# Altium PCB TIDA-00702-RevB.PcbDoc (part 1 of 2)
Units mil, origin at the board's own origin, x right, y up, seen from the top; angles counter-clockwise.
Board outline 3789.41 x 3228.35 mil, 2 copper layers (Top Layer, Bottom Layer), stack 62 mil thick; 129 components, 54 nets, 298 pads, 91 vias.
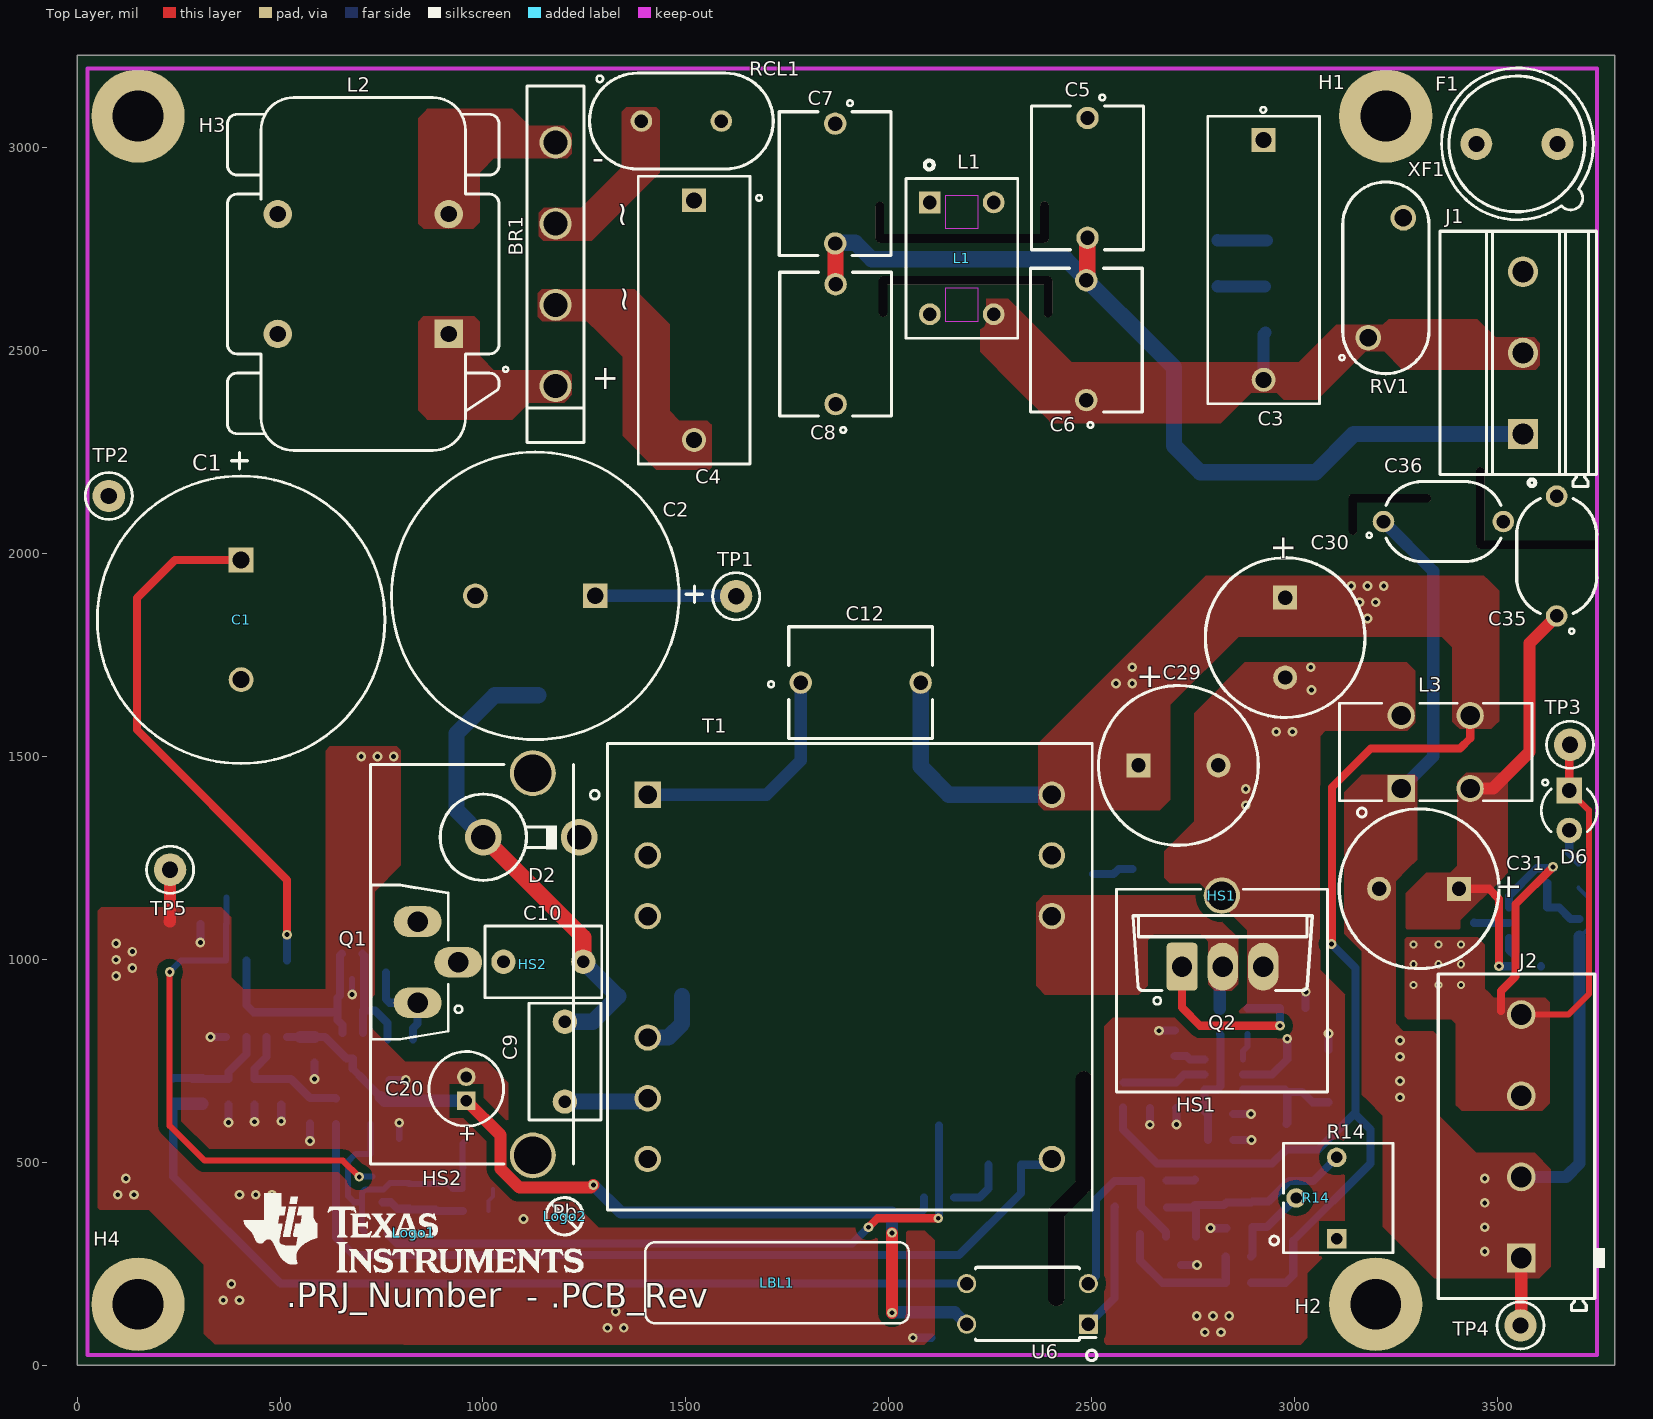
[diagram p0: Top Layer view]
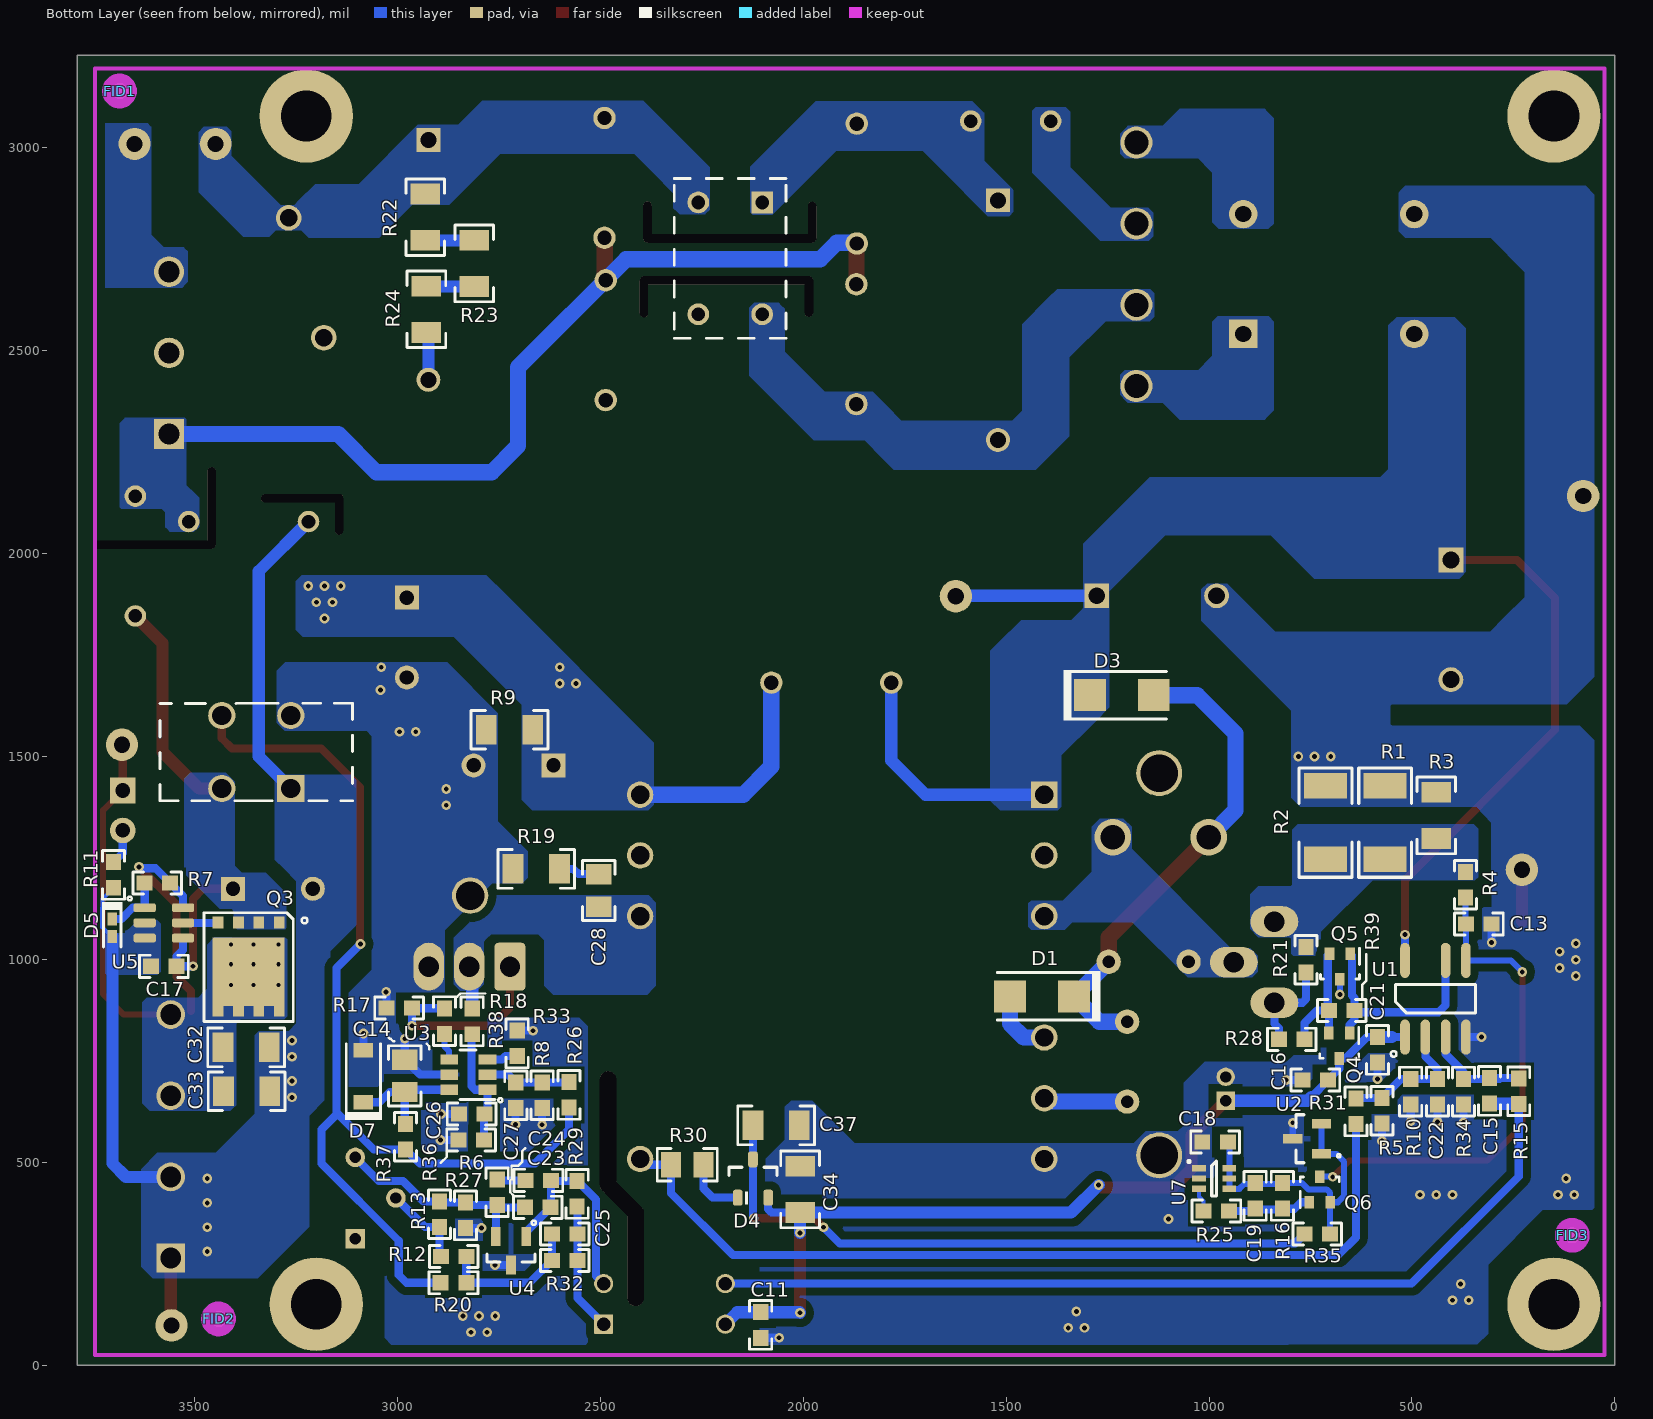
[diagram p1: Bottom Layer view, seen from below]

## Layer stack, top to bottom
Top Solder: solder mask 0.4, Solder Resist, Dk 3.5
Top Layer: signal copper 1.4
Dielectric1: core 59.2, FR-4, Dk 4.8
Bottom Layer: signal copper 1.4
Bottom Solder: solder mask 0.4, Solder Resist, Dk 3.5

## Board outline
0,0 0,3228.35 3789.41,3228.35 3789.41,0

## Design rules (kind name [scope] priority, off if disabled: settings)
AcuteAngle [All] p1: minimum=4.50000000000000E+0001 checktracksonly=FALSE
AssemblyTestPointUsage [All] p1: valid=2
Clearance Clearance_1 [IsSMTPin vs IsVia] p1: gap=8
Clearance Clearance_Poly [InPolygon] p2: gap=20
Clearance [All] p3: gap=8
ComponentClearance ComponentClearance_Shunt [InComponentClass('Header') vs InComponentClass('Shunt')] p1: gap=0 collisioncheckmode=3 verticalgap=0 showdistances=FALSE
ComponentClearance ComponentClearance_MountingHoles_FiducialMarks [InComponentClass('Mounting Holes') vs InComponentClass('FiducialMark')] p2: gap=20 collisioncheckmode=3 verticalgap=10 showdistances=FALSE
ComponentClearance ComponentClearance_Logo [InComponentClass('Logo')] p3: gap=0 collisioncheckmode=3 verticalgap=0 showdistances=FALSE
ComponentClearance ComponentClearance_ScrewToNut [(HasFootprint('NY PMS 440 0025 PH')) vs (HasFootprint('Keystone_1902C'))] p4: gap=5 collisioncheckmode=3 verticalgap=10 showdistances=FALSE
ComponentClearance ComponentClearance_MountingHoles [InComponentClass('Mounting Holes')] p5: gap=50 collisioncheckmode=3 verticalgap=100000 showdistances=FALSE
ComponentClearance ComponentClearance_SmallPassives [HasFootprint('0201*') or HasFootprint('0402*') or HasFootprint('0508') or HasFootprint('0603*') or HasFootprint('0612') or HasFootprint('0805*') or HasFootprint('0815*') or HasFootprint('0830*') or HasFootprint('1206*') or HasFootprint('1210*') or HasFootprint('1808*') or HasFootprint('1812*') or HasFootprint('1825*') or HasFootprint('2010*') or HasFootprint('2220*') or HasFootprint('2225*') or HasFootprint('2512*') or HasFootprint('2728*') or HasFootprint('3518*') vs HasFootprint('0201*') or HasFootprint('0402*') or HasFootprint('0508') or HasFootprint('0603*') or HasFootprint('0612') or HasFootprint('0805*') or HasFootprint('0815*') or HasFootprint('0830*') or HasFootprint('1206*') or HasFootprint('1210*') or HasFootprint('1808*') or HasFootprint('1812*') or HasFootprint('1825*') or HasFootprint('2010*') or HasFootprint('2220*') or HasFootprint('2225*') or HasFootprint('2512*') or HasFootprint('2728*') or HasFootprint('3518*')] p6: gap=10 collisioncheckmode=3 verticalgap=10 showdistances=FALSE
DiffPairsRouting [All] p1: maxlimit=100 minlimit=10 mostfreqgap=10 toplayer_minwidth=15 toplayer_maxwidth=15 toplayer_prefwidth=15 bottomlayer_minwidth=15 bottomlayer_maxwidth=15 bottomlayer_prefwidth=15 maxuncoupledlength=1000
FabricationTestPointUsage TestPointUsage [All] p1: valid=2 allowmultiple=FALSE
FabricationTestpoint Testpoint [All] p1: side=3 testpointundercomponent=TRUE minsize=40 maxsize=100 preferedsize=60 minholesize=0 maxholesize=40 preferedholesize=32 testpointgrid=1 allowsidetop=TRUE allowsidebottom=TRUE usegrid=TRUE gridtolerance=0.01
FanoutControl Fanout_LCC [IsLCC] p1: bgadir=Out bgaviamode=Centered fanoutstyle=Auto fanoutdirection=Alternating viagrid=1 // Fanout_LCC (Default Rule)
FanoutControl Fanout_BGA [IsBGA] p2: bgadir=Out bgaviamode=Centered fanoutstyle=Auto fanoutdirection=Alternating viagrid=1 // Fanout_BGA (Default Rule)
FanoutControl Fanout_Default [All] p4: bgadir=Out bgaviamode=Centered fanoutstyle=Auto fanoutdirection=Alternating viagrid=1 // Fanout_Default (Default Rule)
FanoutControl Fanout_Small [(CompPinCount < 5)] p5: bgadir=Out bgaviamode=Centered fanoutstyle=Auto fanoutdirection=OutThenIn viagrid=1 // Fanout_Small (Default Rule)
Height [All] p1: minheight=0 maxheight=2000 prefheight=100
HoleSize [All] p1: absolutevalues=TRUE maxlimit=251 minlimit=8 maxpercent=80.000 minpercent=20.000
MinimumAnnularRing MinimumAnnularRing_ThermalPadVias [IsVia and InAnyComponent] p1: minimumring=5.91
MinimumAnnularRing [All] p2: minimumring=9
MinimumSolderMaskSliver MinimumSolderMaskSliver_Logo [InComponentClass('Logo') vs InComponentClass('Logo')] p1: minsoldermaskwidth=0.7
MinimumSolderMaskSliver [All] p2: minsoldermaskwidth=3.94
PlaneConnect [All] p1: planeconnectstyle=Direct reliefexpansion=10 reliefentries=4 reliefconductorwidth=10 reliefairgap=10
PolygonConnect [All] p1: connectstyle=Direct reliefconductorwidth=10 reliefentries=4 polygonreliefangle="90 Angle" airgapwidth=10
RoutingVias ThermalPadVias [IsVia and InAnyComponent] p1: holewidth=7.87 width=19.68 viastyle="Through Hole" minholewidth=7.87 minwidth=19.68 maxholewidth=12.99 maxwidth=23.62
RoutingVias [All] p2: holewidth=12 width=24 viastyle="Through Hole" minholewidth=7.87 minwidth=24 maxholewidth=16 maxwidth=34
SilkToSilkClearance SilkToSilkClearance_Pb-FreeLogo [(HasFootprint('Pb-Free_Overlay_Medium') OR HasFootprint('Pb-Free_Overlay_Small')) vs (HasFootprint('Pb-Free_Overlay_Medium') OR HasFootprint('Pb-Free_Overlay_Small'))] p1: silktosilkclearance=0
SilkToSilkClearance [All] p2: silktosilkclearance=5
SilkToSolderMaskClearance SilkscreenOverComponentPads [IsPad] p1: minsilkscreentomaskgap=1 clearancetoexposedcopper=TRUE
SolderMaskExpansion [All] p1: expansion=2.5
UnpouredPolygon [All] p1: allowunpoured=FALSE
Width [All] p1: maxlimit=120 minlimit=6 preferedwidth=10 checkconnectedcopper=TRUE
14 further rules are at their usual default settings.

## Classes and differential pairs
component class Logo: Logo1
component class Hardware_ANSI-B: !PCB1 FID1 FID2 FID3 H1 H2 H3 H4 LBL1 Logo1 Logo2 Logo3 ZZ1 ZZ2 ZZ3 ZZ4
component class FiducialMark: FID1 FID2 FID3
component class AssemblyNote: ZZ1 ZZ2 ZZ3 ZZ4
component class Label: LBL1
component class TIDA00702_Flyback: BR1 C1 C2 C3 C4 C5 C6 C7 C8 C9 C10 C11 C12 C13 C14 C15 C16 C17 C18 C19 C20 C21 C22 C23 C24 C25 C26 C27 C28 C29 C30 C31 C32 C33 C34 C35 C36 C37 D1 D2 D3 D4 D5 D6 D7 F1 HS1 HS2 J1 J2 L1 L2 L3 Q1 Q2 Q3 Q4 Q5 Q6 R1 R2 R3 R4 R5 R6 R7 R8 R9 R10 R11 R12 R13 R14 R15 R16 R17 R18 R19 R20 R21 R22 R23 R24 R25 R26 R27 R28 R29 R30 R31 R32 R33 R34 R35 R36 R37 R38 R39 R54 RCL1 RV1 T1 TP1 TP2 TP3 TP4 TP5 U1 U2 U3 U4 U5 U6 U7 XF1

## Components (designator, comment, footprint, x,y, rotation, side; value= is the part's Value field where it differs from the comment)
BR1 "GBU6J" GBU 1179,2713 r90 top
C1 "UCY2W820MHD6" CAPPRD750W80D1800H3150 404,1837 r270 top
C2 "UCY2W820MHD6" CAPPRD750W80D1800H3150 1129,1896 r180 top
C3 "B32922C3224M" B32922_12.5mm 2924,2723.65 r270 top
C4 "B32922C3224M" B32922_12.5mm 1520.36,2575.51 r270 top
C5 "C907U102MYVDBA7317" E_900x700x900 2490,2926 r270 top
C6 "C907U102MYVDBA7317" E_900x700x900 2487,2526 r90 top (schematic designator C5)
C7 "CS80ZU2GA222MYNKA" E_900x700x900 1868,2912 r270 top (schematic designator C39)
C8 "CS80ZU2GA222MYNKA" E_900x700x900 1869,2516 r90 top (schematic designator C43)
C9 "B32529C8103K" B32529_450x950x730 1202,748 r270 top
C10 "B32529C8103K" B32529_450x950x730 1149,994 r180 top (schematic designator C34)
C11 "C1608X7R1H104K" 0603 2105,99 r270 bottom
C12 "CS80ZU2GA222MYNKA" E_900x700x900 1931,1682 r0 top (schematic designator C35)
C13 "06035A5R6CAT2A" 0603 335,1087 r180 bottom
C14 "GRM21BR71H474KA88L" 0805_HV 2982,713 r270 bottom (schematic designator C37)
C15 "C1608X7R1H473K" 0603 308.77,675.84 r270 bottom (schematic designator C38)
C16 "C1608X7R1H104K" 0603 738,703 r0 bottom
C17 "GRM188R61H105KAALD" 0603 3575.76,983 r0 bottom (schematic designator C34)
C18 "C1608X7R1C224K" 0603 985.27,549.98 r0 bottom
C19 "GRM188R61C104KA01D" 0603 886.27,416.98 r90 bottom
C20 "UVR1H100MDD6TP" FC_400x1100 959,681 r90 top
C21 "C1608X7R1H104K" 0603 585,777 r270 bottom
C22 "06035A4R7CAT2A" 0603 437,674 r270 bottom
C23 "C1608C0G1H102J" 0603 2652.76,455.42 r0 bottom
C24 "C1608C0G1H102J" 0603 2654.27,389 r0 bottom
C25 "06035A100JAT2A" 0603 2587.84,323 r180 bottom
C26 "06035A2R2CAT2A" 0603 2817.47,619 r0 bottom
C27 "06035A470JAT2A" 0603 2708.47,665 r90 bottom
C28 "C2012X7R2E103K" 0805_HV 2504,1170 r270 bottom
C29 "EEU-FR1V821L" CAPPR5-10X20 2714,1478 r0 top
C30 "EEU-FR1V821L" CAPPR5-10X20 2977,1793 r270 top
C31 "EEU-FR1V681" CAPPR5-10X20 3307,1174 r180 top
C32 "C3216X7R1H105K" 1206 3373,783 r180 bottom
C33 "C1206C104J5RACTU" 1206 3372,675 r180 bottom
C34 "C3216X7R1H105K" 1206 2008,433 r90 bottom
C35 "VY2472M49Y5US63V7" CAPRD750W60D750H1050 3646,1994 r90 top
C36 "VY2472M49Y5US63V7" CAPRD750W60D750H1050 3367,2079 r0 top
C37 "C3216X7R1H105K" 1206 2067,591 r180 bottom
D1 "BYG21M-E3/TR" SMA 1412,909 r0 bottom (schematic designator D8)
D2 "1.5KE150A" DO-201AD_Vert 1119,1301 r180 top
D3 "BYG21M-E3/TR" SMA 1215,1651 r180 bottom
D4 "BAV23S-7-F" SOT-23 2124,460 r90 bottom
D5 "BZT52C4V7T-7" SOD-523 3702.76,1078 r270 bottom (schematic designator D13)
D6 "HLMP1503" LED_HLMP1523 3677,1367 r270 top
D7 "MMSZ5252B-7-F" SOD-123 3084,712 r90 bottom (schematic designator D11)
F1 "37212500001" FUSE_372 3548,3009.65 r0 top
FID1 "Fiducial" Fiducial10-20 3685,3140 r180 bottom
FID2 "Fiducial" Fiducial10-20 3441,114 r180 bottom
FID3 "Fiducial" Fiducial10-20 105,320 r180 bottom
H1 "PMSSS 440 0025 PH" B_F_PMSSS4400025PH 3225,3078.35 r0 top
H2 "PMSSS 440 0025 PH" B_F_PMSSS4400025PH 3200,150 r0 top (schematic designator H1)
H3 "PMSSS 440 0025 PH" B_F_PMSSS4400025PH 150,3078.35 r0 top (schematic designator H1)
H4 "PMSSS 440 0025 PH" B_F_PMSSS4400025PH 150,150 r0 top (schematic designator H1)
HS1 "V7237C" HEATSINK_V7237C 2821,923 r0 top (schematic designator HS3)
HS2 "593002B00000G" HEATSINK_593002B03400G 973,988 r90 top (schematic designator HS1)
J1 "1715734" Phoenix_1715734 3563,2494.65 r90 top
J2 "1715747" Phoenix_1715747 3559,564 r90 top
L1 "750343092" 750311982 2180,2727.65 r270 top (schematic designator L2)
L2 "744823220" IND_WE-CMB_M 705,2689 r180 top (schematic designator L1)
L3 "750343094" IND_750343094 3348,1511 r0 top (schematic designator L4)
LBL1 "Size: 0.65\" x 0.20 \"" Label_650x200 1725,203 r0 top
Logo1 "Texas Instruments" TI_STACKED_OVERLAY_SMALL 829,326 r0 top
Logo2 "Pb-Free Symbol" Pb-Free_Overlay_Small 1201,367 r0 top
Logo3 "FCC disclaimer" FCC_disclaimer 1355,3340 r0 top
Q1 "AOTF11S65L" TO-220_FullPAK_Offset 839,993 r90 top (schematic designator Q2)
Q2 "IRFI4227PBF" TO-220AB 2823,982 r0 top (schematic designator Q3)
Q3 "CSD18504Q5A" TRANS_NexFET_Q5A 3366.89,981.03 r270 bottom (schematic designator Q4)
Q4 "MMBT4401WT1G" SOT-323 679,787 r270 bottom (schematic designator Q1)
Q5 "MMBT4403WT1G" SOT-323 677.59,982.5 r270 bottom
Q6 "MMBT4403WT1G" SOT-323 727.27,432.98 r90 bottom
R1 "CSRN2010FKR250" 2010 566,1337 r270 bottom (schematic designator R26)
R2 "CRCW201012R1FKEF" 2010 713,1337 r90 bottom (schematic designator R4)
R3 "CRCW1206100RFKEA" 1206 440,1355 r270 bottom
R4 "CRCW06031K27FKEA" 0603 368,1184 r90 bottom (schematic designator R2)
R5 "CRCW060316K9FKEA" 0603 573.8,627 r270 bottom
R6 "CRCW06034K99FKEA" 0603 2754.27,426 r90 bottom (schematic designator R51)
R7 "CRCW060310K0FKEA" 0603 3592,1188 r0 bottom (schematic designator R52)
R8 "CRCW060347K5FKEA" 0603 2643.47,665 r270 bottom (schematic designator R41)
R9 "CRCW1206100KFKEA" 1206 2724,1566 r180 bottom (schematic designator R53)
R10 "RC0603FR-07470KL" 0603 503,674 r90 bottom (schematic designator R54)
R11 "CRCW06031K21FKEA" 0603 3700,1208 r90 bottom (schematic designator R55)
R12 "CRCW0603332KFKEA" 0603 2861.27,268 r180 bottom (schematic designator R56)
R13 "CRCW0603100KFKEA" 0603 2896.27,372 r270 bottom (schematic designator R57)
R14 "25PR100KLF" POT_25PXXXXXX 3108,412 r90 top (schematic designator R58)
R15 "CRCW0603100KFKEA" 0603 236.77,674.84 r90 bottom (schematic designator R60)
R16 "CRCW0603100KFKEA" 0603 819.27,416.98 r90 bottom (schematic designator R61)
R17 "CRCW060320K0FKEA" 0603 2996,880 r0 bottom (schematic designator R43)
R18 "CRCW06031R50FKEA" 0603 2884,848 r90 bottom (schematic designator R44)
R19 "CRCW1206100RFKEA" 1206 2658,1223 r0 bottom (schematic designator R45)
R20 "CRCW060347R5FKEA" 0603 2862,203 r180 bottom (schematic designator R46)
R21 "CRCW0603100KFKEA" 0603 761,999 r270 bottom (schematic designator R47)
R22 "CRCW1206750KFKEA" 1206 2931.64,2829.06 r270 bottom
R23 "CRCW1206750KFKEA" 1206 2810.64,2715.06 r270 bottom
R24 "CRCW1206750KFKEA" 1206 2928.64,2602.06 r270 bottom
R25 "CRCW060310K0FKEA" 0603 981.91,379.98 r180 bottom
R26 "CRCW0603750KFKEA" 0603 2577.47,666 r90 bottom (schematic designator R42)
R27 "CRCW060344K2FKEA" 0603 2832.27,369 r270 bottom (schematic designator R48)
R28 "CRCW06035R11FKEA" 0603 796.28,803.04 r0 bottom
R29 "CRCW06031K00FKEA" 0603 2557.27,422 r270 bottom (schematic designator R49)
R30 "CRCW080547R5FKEA" 0805_HV 2286,494 r180 bottom
R31 "CRCW060371K5FKEA" 0603 637.8,625.49 r270 bottom
R32 "CRCW06031K50FKEA" 0603 2587.84,258 r180 bottom (schematic designator R50)
R33 "CRCW060310K0FKEA" 0603 2705,793 r90 bottom (schematic designator R40)
R34 "CRCW060320K5FKEA" 0603 372.73,674 r90 bottom
R35 "CRCW060313K7FKEA" 0603 733.4,323.09 r180 bottom
R36 "CRCW060310K0FKEA" 0603 2818.47,555 r180 bottom (schematic designator R39)
R37 "CRCW0603402RFKEA" 0603 2980,563 r90 bottom
R38 "CRCW0603750KFKEA" 0603 2816,847 r90 bottom
R39 "CRCW06030000Z0EA" 0603 673,874 r0 bottom
RCL1 "B57236S479M" THERM_B57236S0 1489,3066 r0 top
RV1 "S10K275E2" VAR_S10K275E2 3225,2679.65 r90 top
T1 "" Trans_FBtrans00702 1904,957 r0 top
TP1 "5000" Keystone5000 1624,1895 r0 top (schematic designator TP5)
TP2 "5001" Keystone5001 78,2142 r0 top (schematic designator TP6)
TP3 "5000" Keystone5000 3679,1529 r0 top
TP4 "5001" Keystone5001 3557,98 r0 top
TP5 "5001" Keystone5001 229,1221 r0 top (schematic designator TP7)
U1 "UCC28740DR" D0007A_N 442,903 r90 bottom (schematic designator U2)
U2 "TL431BQDBZ" DBZ0003A_L 758.27,557.98 r0 bottom (schematic designator U1)
U3 "UCC24636DBV" DBV0006A_N 2825.47,716 r0 bottom
U4 "TL431BQDBZ" DBZ0003A_L 2720.27,282 r270 bottom
U5 "LM5050-2" tsop-6 3575.76,1090 r180 bottom
U6 "LTV-817" DIP762W60P254L460H350Q4B 2342,151 r180 top
U7 "TMP302CIDCK" DCK0006A_N 987.27,459.98 r180 bottom
XF1 "56000001009" FuseHolder_560000010 3548,3009.65 r0 top
ZZ1 "This Assembly Note is for PCB labels only" AssemblyNoteLabel -739,3593 r0 top
ZZ2 "These assemblies are ESD sensitive, ESD precautions shall be observed." AssemblyNote -738,3513 r0 top
ZZ3 "These assemblies must be clean and free from flux and all contaminants. Use of no clean flux is not acceptable." AssemblyNote -738,3424.44 r0 top
ZZ4 "These assemblies must comply with workmanship standards IPC-A-610 Class 2, unless otherwise specified." AssemblyNote -738,3335.89 r0 top

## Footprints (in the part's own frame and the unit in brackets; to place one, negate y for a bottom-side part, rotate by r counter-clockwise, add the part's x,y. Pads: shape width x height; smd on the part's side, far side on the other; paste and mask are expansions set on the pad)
0603 [mm] "0603 from SM-752 data"
  rect 1x0.95 smd: 1(-0.8,0) 2(0.8,0)
  silkscreen extent -1.52,-0.69 1.52,0.69, body extent -0.87,-0.47 0.87,0.47, height 0.85
0805_HV [mil] "0805 with 30mil clearance between pads"
  rect 50x63 smd: 1(-40,0) 2(40,0)
  silkscreen extent -74,-40 74,40, body extent -43,-29 43,29, height 43
1206 [mm] "1206 from SM-752 data"
  rect 1.3x1.85 smd: 1(-1.45,0) 2(1.45,0)
  silkscreen extent -2.4,-1.21 2.4,1.21, body extent -1.7,-0.9 1.7,0.9, height 1.35
2010 [mm] "Chip Capacitor, Body 5.08x2.54mm, IPC Medium Density"
  rect 1.6x2.7 smd: 1(-2.3,0) 2(2.3,0)
  silkscreen extent -3.42,-1.65 3.42,1.65, body extent -2.73,-1.45 2.73,1.45, height 1.66
750311982 [mm] "4 LEAD,TH"
  rect 1.362x1.362 / inner round 1.362 / far side rect 1.362x1.362 hole 0.854: 1(-3.5,-2)
  round 1.362 hole 0.854: 2(-3.5,2) 3(3.5,2) 4(3.5,-2)
  Top Layer keep-out region: 1.874,-1.024 3.928,-1.024 3.928,1.03 1.874,1.03
  Top Layer keep-out region: -3.926,-1.024 -1.872,-1.024 -1.872,1.03 -3.926,1.03
  silkscreen extent -6.12,-3.5 5,3.5, body extent -5,-3.5 5,3.5, height 6.8
AssemblyNote [mil] "Assembly Note"
AssemblyNoteLabel [mil] "Assembly Note for PCB Labels"
B32529_450x950x730 [mil] "EPCOS"
  round 60 hole 31: 1(-98.43,0) 2(98.43,0)
  silkscreen extent -144,-89 144,89, body extent -144,-89 144,89, height 374
B32922_12.5mm [mm] "Epcos film capacitors, 15mm spacing"
  rect 1.5x1.5 hole 1: 1(-7.5,0)
  round 1.5 hole 1: 2(7.5,0)
  silkscreen extent -9,-3.5 9,3.5, body extent -9,-3.5 9,3.5, height 12.5
B_F_PMSSS4400025PH [mil] "MACHINE SCREW PAN PHILLIPS 4-40"
  round 230 hole 125: 1(0,0)
  body extent -109,-109 110,110, height 79
CAPPR5-10X20 [mm] "Capacitor, Electrolytic, Radial; Body 10 x 20 mm (Dia.xH typ); Pin Spacing 5 mm (typ)"
  rect 1.5x1.5 hole 0.9: 1(-2.5,0)
  round 1.5 hole 0.9: 2(2.5,0)
  silkscreen extent -5,-5 5,5, body extent -5.01,-5.01 5.01,5.01, height 22
CAPPRD750W80D1800H3150 [mm] "CAPACITOR, POLARIZED, 0.8MM LEAD DIA, PITCH 7.5MM"
  rect 1.554x1.554 / inner round 1.554 / far side rect 1.554x1.554 hole 1.054: 1(-3.75,0)
  round 1.554 hole 1.054: 2(3.75,0)
  silkscreen extent -10.46,-9 9,9, body extent -8.93,-8.98 9,8.98, height 33
CAPRD750W60D750H1050 [mm] "Vishay BC Components"
  round 1.35 hole 0.85: 1(-3.75,0) 2(3.75,0)
  silkscreen extent -3.6,-2.51 3.6,2.51, body extent -4.05,-2.5 4.05,2.5, height 10.49
D0007A_N [mm] "SOIC, 7-Leads, Body 4.9x3.9mm, Pitch 1.27mm, IPC Medium Density"
  oval 2.2x0.6 smd: 1(-2.4,1.905) 2(-2.4,0.635) 3(-2.4,-0.635) 4(-2.4,-1.905) 5(2.4,-1.905) 6(2.4,-0.635) 8(2.4,1.905)
  silkscreen extent -0.9,-2.5 0.9,2.5, body extent -3,-2.5 3,2.5, height 1.54
DBV0006A_N [mm] "SOT23, 6-Leads, Body 2.9x1.6mm, Pitch 0.95mm, Lead Span 2.8mm, IPC Medium Density"
  rect 1.1x0.65 smd: 1(-1.2,0.95) 2(-1.2,0) 3(-1.2,-0.95) 4(1.2,-0.95) 5(1.2,0) 6(1.2,0.95)
  silkscreen extent -1.67,-1.55 0.5,1.55, body extent -1.42,-1.46 1.42,1.46, height 1.11
DBZ0003A_L [mm] "SOT23, 3-Leads, Body 2.9x1.3mm, Pitch 0.95mm, Lead Span 2.4mm, IPC High Density"
  rect 1.2x0.6 smd: 1(-0.9,0.95) 2(-0.9,-0.95) 3(0.9,0)
  silkscreen extent 0.2,-1.5 0.7,1.5, body extent -1.26,-1.46 1.26,1.46, height 0.96
DCK0006A_N [mm] "SOT23, 6-Leads, Body 2x1.3mm, Pitch 0.65mm, Lead Span 2.1mm, IPC Medium Density"
  rect 0.85x0.4 smd: 1(-0.95,0.65) 2(-0.95,0) 3(-0.95,-0.65) 4(0.95,-0.65) 5(0.95,0) 6(0.95,0.65)
  silkscreen extent -0.15,-1.1 0.15,1.1, body extent -1.14,-1 1.14,1, height 0.94
DIP762W60P254L460H350Q4B [mm] "LITE-ON"
  rrect8% 1.2x1.2 hole 0.85: 1(-3.81,1.27)
  round 1.2 hole 0.85: 2(-3.81,-1.27) 3(3.81,-1.27) 4(3.81,1.27)
  silkscreen extent -4.34,-2.29 3.25,3.55, body extent -3.94,-2.3 3.94,2.3, height 4.3
DO-201AD_Vert [mm] "DO-201AD VERTICAL FOOTPRINT"
  round 2.3 hole 1.55: 1(-3,0) 2(3,0)
  silkscreen extent -1.62,-2.7 5.7,2.7, body extent -3.66,-2.66 5.66,2.65, height 14.8
E_900x700x900 [mm] "TH, 2- Leads, Body 9x7mm, Pin Spacing 7.5mm"
  round 1.4 hole 0.9: 1(-3.75,0) 2(3.75,0)
  silkscreen extent -4.5,-3.5 4.5,3.5, body extent -4.49,-3.5 4.49,3.5, height 11.96
FC_400x1100 [mm] "Panasonic"
  rect 1.15x1.15 hole 0.7: 1(-0.75,0)
  round 1.15 hole 0.7: 2(0.75,0)
  silkscreen extent -2.33,-2.33 2.33,2.33, body extent -2.23,-2.25 2.25,2.25, height 12.01
FCC_disclaimer [mil]
Fiducial10-20 [mm]
  round 1 smd mask+0.5: 1(0,0)
  Top Layer keep-out circle w1.178: c0,0 r0.5
FUSE_372 [mm] "LITTELFUSE"
  round 1.5 hole 1: 1(-2.54,0) 2(2.54,0)
  silkscreen extent -4.25,-4.25 4.25,4.25, body extent -4.26,-4.26 4.26,4.26, height 8
FuseHolder_560000010 [mm] "Littelfuse fuse holder TR5"
  round 2 hole 1: 1(-2.54,0) 2(2.54,0)
  silkscreen extent -4.71,-4.75 4.79,4.75, body extent -4.75,-4.74 4.75,4.75, height 5.6
GBU [mm] "Comchip / Diodes Inc diode bridge"
  round 2 hole 1.5: 1(-7.62,0) 2(-2.54,0) 3(2.54,0) 4(7.62,0)
  silkscreen extent -11.15,-1.78 11.15,1.78, body extent -11.15,-1.76 11.15,1.8, height 21.55
HEATSINK_593002B03400G [mm] "HEATSINK, 25X12.7X29.97 MM"
  round 2.868 hole 2.36: 1(-11.965,-3.81) 1(11.965,-3.81)
  silkscreen extent -12.5,-6.35 12.5,6.35, body extent -12.5,-6.35 12.5,6.35, height 29.97
HEATSINK_V7237C [mm] "HEATSINK,TO-220,13.21X12.7MM"
  round 2.28 hole 1.78: 1(0,5.95)
  silkscreen extent -6.61,-6.35 6.61,6.35, body extent -6.61,-6.35 6.61,6.35, height 19.05
IND_750343094 [mm] "INDUCTOR, TH-4P"
  rect 1.7x1.7 / inner round 1.7 / far side rect 1.7x1.7 hole 1.2: 1(-2.16,-2.285)
  round 1.7 hole 1.2: 2(2.16,-2.285) 3(-2.16,2.285) 4(2.16,2.285)
  silkscreen extent -6.03,-4.06 6.03,3.05, body extent -6.03,-3.05 6.03,3.05, height 13.06
IND_WE-CMB_M [mil] "Wurth"
  rect 70x70 hole 40: 1(-210.63,147.64)
  round 70 hole 40: 2(210.63,147.64) 3(210.63,-147.64) 4(-210.63,-147.64)
  silkscreen extent -335,-435 335,435, body extent -335,-394 335,394, height 1044
Keystone5000 [mil] "For Keystone 500x miniature loop terminals"
  round 80 hole 40: 1(0,0)
  silkscreen extent -58,-58 58,58, body extent -49,-49 49,49, height 182
Keystone5001 [mil] "For Keystone 500x miniature loop terminals"
  round 80 hole 40: 1(0,0)
  silkscreen extent -58,-58 58,58, body extent -49,-49 49,49, height 182
Label_650x200 [mil] "Thermal Transfer Label"
  silkscreen extent -325,-100 325,100, body extent -326,-101 326,101, height 1
LED_HLMP1523 [mm] "Everlight Electronics"
  rect 1.6x1.6 hole 0.914: 1(-1.25,0)
  round 1.6 hole 0.914: 2(1.25,0)
  silkscreen extent -1.34,-1.75 1.34,1.75, body extent -1.6,-1.67 1.68,1.67, height 6.2
Pb-Free_Overlay_Small [mil]
  silkscreen extent -46,-46 46,46
Phoenix_1715734 [mm] "Phoenix"
  rect 1.9x1.9 hole 1.321: 1(-5.08,0)
  round 1.9 hole 1.321: 2(0,0) 3(5.08,0)
  silkscreen extent -8.36,-4.6 7.62,63.83, body extent -8.36,-4.6 7.62,5.2, height 14.2
Phoenix_1715747 [mm] "Terminal Block, 5.08mm, 4x1, TH"
  rect 1.8x1.8 hole 1.3: 1(-7.62,0)
  round 1.8 hole 1.3: 2(-2.54,0) 3(2.54,0) 4(7.62,0)
  silkscreen extent -10.9,-5.25 10.16,5.2, body extent -10.9,-4.6 10.16,5.2, height 14.2
POT_25PXXXXXX [mm] "Potentiometer, 25p series, through hole, 3 pin"
  rect 1.222x1.222 hole 0.714: 1(-2.54,0.1)
  round 1.222 hole 0.714: 2(0,2.64) 3(2.54,0.1)
  silkscreen extent -3.43,-3.43 3.43,4.29, body extent -3.43,-3.43 3.43,3.43, height 5.13
SMA [mm] "Molded Diode, 2-Leads, Body 4.3x2.6mm, IPC Medium Density, based on OnSemi component dimensions and land pattern"
  rect 2x2 smd: 1(-2,0) 2(2,0)
  silkscreen extent -3.66,-1.57 2.79,1.57, body extent -2.6,-1.3 2.6,1.3, height 2.42
SOD-123 [mm] "On Semi recommended land pattern"
  rect 0.915x1.22 smd: 1(-1.637,0) 2(1.637,0)
  silkscreen extent -2.75,-1.17 2.03,1.17, body extent -1.93,-0.9 1.93,0.9, height 1.35
SOD-523 [mm] "NXP Semiconductor recommended land pattern, nominal STEP model"
  rect 0.8x0.6 smd paste-0.05: 1(-0.55,0) 2(0.55,0)
  silkscreen extent -1.6,-0.64 1.2,0.63, body extent -0.8,-0.4 0.8,0.4, height 0.72
SOT-23 [mm] "SOT23, 3-Leads, Body 2.9x1.3mm, Pitch 0.95mm, Lead Span 2.5mm, IPC Medium Density"
  rrect50% 1x0.6 smd: 1(-1.2,0.95) 2(-1.2,-0.95) 3(1.2,0)
  silkscreen extent -1.62,-1.5 0.7,1.5, body extent -1.16,-1.45 1.21,1.45, height 1
SOT-323 [mm] "Zetex recommended land pattern.  March 2007"
  rect 0.8x0.6 smd: 1(-0.8,0.65) 2(-0.8,-0.65) 3(0.8,0)
  silkscreen extent -1.14,-1.22 0.77,1.22, body extent -1.13,-1.13 1.12,1.12, height 1.13
THERM_B57236S0 [mm] "EPCOS"
  round 1.35 hole 0.85: 1(-2.5,0) 2(2.5,0)
  silkscreen extent -5.75,-3 5.75,3, body extent -5.75,-3 5.7,3, height 15.99
TI_STACKED_OVERLAY_SMALL [mil]
  silkscreen extent -418,-98 418,98
TO-220_FullPAK_Offset [mil] "Infineon  PG-TO220-3-31"
  oval 76x118.11 hole 50: 1(-100,0) 2(0,-100) 3(100,0)
  silkscreen extent -190,-75 190,115, body extent -190,-112 190,115, height 902
TO-220AB [mil] "Copied from Altium's version of TO3B"
  rrect25% 76x118.11 hole 50: 1(-100,0)
  oval 76x118.11 hole 50: 2(0,0) 3(100,0)
  silkscreen extent -221,-59 221,126, body extent -221,-59 221,126, height 765
Trans_FBtrans00702 [mm] "TRANSFORMER, VERTICAL, THT, 12-PIN"
  rect 1.65x1.65 / inner round 1.65 / far side rect 1.65x1.65 hole 1.15: 1(-12.65,11.4)
  round 1.65 hole 1.15: 2(-12.65,7.6) 3(-12.65,3.8) 4(-12.65,-3.8) 5(-12.65,-7.6) 6(-12.65,-11.4) 7(12.65,-11.4) 10(12.65,3.8) 11(12.65,7.6) 12(12.65,11.4)
  round 0 all layers, no hole: 8(12.65,-7.6) 9(12.65,-3.8)
  silkscreen extent -16.24,-14.6 15.17,14.6, body extent -15.24,-14.6 15.24,14.6, height 29.3
TRANS_NexFET_Q5A [mm] "TI recommended land pattern (nominal) M0139-01"
  rect 0.75x0.675 smd paste-0.1: 1(-2.776,1.917) 2(-2.776,0.639) 3(-2.776,-0.639) 4(-2.776,-1.917)
  rect 0.655x0.675 smd paste-0.1: 5(2.776,-1.917) 6(2.776,-0.639) 7(2.776,0.639) 8(2.776,1.917)
  rect 4.295x4.51 smd paste-2.2: 9(0.301,0)
  silkscreen extent -3.4,-2.8 3.4,2.8, body extent -3.05,-2.5 3.05,2.5, height 1.11
tsop-6 [mm] "TSOP, 6-Leads, Body 3.1x1.7mm (max), Pitch 0.95mm, IPC Medium Density"
  rrect50% 1.4x0.55 smd: 1(-1.2,0.95) 2(-1.2,0) 3(-1.2,-0.95) 4(1.2,-0.95) 5(1.2,0) 6(1.2,0.95)
  silkscreen extent -2.26,1.4 -2.02,1.65, body extent -0.85,-1.55 0.85,1.55, height 1.1
VAR_S10K275E2 [mm] "EPCOS"
  round 1.6 hole 1.1: 1(-3.75,1.1) 2(3.75,-1.1)
  silkscreen extent -6,-2.7 6,2.7, body extent -5.98,-2.7 5.98,2.7, height 14.99

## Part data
BR1: library part GBU4A-BP, "RECT BRIDGE GPP 6A 600V GBU"
C1 C2: library part EEUED2E820S, "CAP ALUM 82UF 20% 450V RADIAL"
C3 C4: "CAP, Film, 0.22 µF, 630 V, +/- 20%, TH"
C5 C6: library part DE6E3KJ222MN3A, "CAP CER 1000PF 400VAC Y5V RADIAL"
C7 C8 C12: library part DE6E3KJ222MN3A, "CAP CER 2200PF 300VAC 20% RADIAL"
C9 C10: library part B32529C6223J, "CAP FILM 10000PF 10% 630VDC RAD"
C11 C16 C21: "CAP, CERM, 0.1 µF, 50 V, +/- 10%, X7R, 0603"
C13: "CAP, CERM, 5.6 pF, 50 V, +/- 5%, C0G/NP0, 0603"
C14: "CAP, CERM, 0.47 µF, 50 V, +/- 10%, X7R, 0805"
C15: "CAP, CERM, 0.047 µF, 50 V, +/- 10%, X7R, 0603"
C17: "CAP, CERM, 1 µF, 50 V, +/- 10%, X5R, 0603"
C18: "CAP, CERM, 0.22 µF, 16 V, +/- 10%, X7R, 0603"
C19: "CAP, CERM, 0.1 µF, 16 V, +/- 10%, X5R, 0603"
C20: library part EEU-FC1H100, "CAP ALUM 10UF 20% 50V RADIAL"
C22: "CAP, CERM, 4.7 pF, 50 V, +/- 5%, C0G/NP0, 0603"
C23 C24: "CAP, CERM, 1000 pF, 50 V, +/- 5%, C0G/NP0, 0603"
C25: "CAP, CERM, 10 pF, 50 V, +/- 5%, C0G/NP0, 0603"
C26: "CAP, CERM, 2.2 pF, 50 V, +/- 11%, C0G/NP0, 0603"
C27: "CAP, CERM, 47 pF, 50 V, +/- 5%, C0G/NP0, 0603"
C28: "CAP, CERM, 0.01 µF, 250 V, +/- 10%, X7R, 0805"
C29 C30: library part EEU-FR1V681, "CAP ALUM 820UF 20% 35V RADIAL"
C31: "CAP, AL, 680 µF, 35 V, +/- 20%, TH"
C32 C34 C37: "CAP, CERM, 1 µF, 50 V, +/- 10%, X7R, 1206"
C33: "CAP, CERM, 0.1 µF, 50 V, +/- 5%, X7R, 1206"
C35 C36: library part VY2102M29Y5UG63V7, "CAP CER 4700PF 440VAC Y5U RADIAL"
D1 D3: "Diode, Fast Rectifier, 1000 V, 1.5 A, SMA"
D2: library part SMCJ100A, "TVS DIODE 128VWM 207VC AXIAL"
D4: "Diode, Switching, 200 V, 0.4 A, SOT-23"
D5: "Diode, Zener, 4.7 V, 300 mW, SOD-523"
D6: library part HLMP1523, "LED SS HI EFF GREEN DIFF 3MM"
D7: "Diode, Zener, 24V, 500mW, SOD-123"
F1: "Fuse, 2.5 A, 250 V, TH"
FID1 FID2 FID3: "Fiducial mark.  There is nothing to buy or mount."
H1 H2 H3 H4: "MACHINE SCREW PAN PHILLIPS 4-40"
HS1: library part 593002B00000G, "HEATSINK TO-220 19.05X13.21MM"
HS2: "HEATSINK TWISTED FIN TO-220 Vertical"
J1: "TERM BLOCK 3POS 5.08MM, TH"
J2: "Terminal Block, 5.08mm, 4x1, TH"
L1: library part 744823210, "Coupled inductor, 7mH, 2 A, 0.045 ohm,+/-32%"
L2: library part 744823210, "Coupled inductor, 20 mH, 1.5A, 0.270 ohm, +/- 30%, TH"
L3: library part 744823210, "Coupled inductor, 7mH, 2 A, 0.045 ohm, 3.7-7.1 mH"
LBL1: library part THT-14-423-10, "Thermal Transfer Printable Labels, 0.650\" W x 0.200\" H - 10,000 per roll"
Logo1: library part TI_Logo, "Texas Instrument Corporate Signature"
Logo2: library part Pb-Free
Logo3: library part FCC_disclaimer, "FCC_disclaimer"
Q1: library part IPP50R199CP, "MOSFET N-CH 650V 11A TO220F"
Q2: library part IRFB4410ZPBF, "MOSFET N-CH 200V 26A TO-220FP"
Q3: "MOSFET, N-CH, 40 V, 15 A, SON 5x6mm"
Q4: library part "CMST2222A TR, Central Semiconductor", "Transistor, NPN, 40 V, 0.6 A, SOT-323"
Q5 Q6: library part "MMBT2907A, Fairchild Semiconductor", "Transistor, PNP, 40 V, 0.6 A, SOT-323"
R1: "RES, 0.25, 1%, 1 W, 2010"
R2: "RES, 12.1, 1%, 0.75 W, 2010"
R3 R19: "RES, 100, 1%, 0.25 W, 1206"
R4: "RES, 1.27 k, 1%, 0.1 W, 0603"
R5: "RES, 16.9 k, 1%, 0.1 W, 0603"
R6: "RES, 4.99 k, 1%, 0.1 W, 0603"
R7 R25 R33 R36: "RES, 10.0 k, 1%, 0.1 W, 0603"
R8: "RES, 47.5 k, 1%, 0.1 W, 0603"
R9: "RES, 100 k, 1%, 0.25 W, 1206"
R10: "RES, 470 k, 1%, 0.1 W, 0603"
R11: "RES, 1.21 k, 1%, 0.1 W, 0603"
R12: "RES, 332 k, 1%, 0.1 W, 0603"
R13 R15 R16 R21: "RES, 100 k, 1%, 0.1 W, 0603"
R14: library part 3266W-1-203LF, "TRIMMER 100K OHM 0.5W TH"
R17: "RES, 20.0 k, 1%, 0.1 W, 0603"
R18: "RES, 1.50, 1%, 0.1 W, 0603"
R20: "RES, 47.5, 1%, 0.1 W, 0603"
R22 R23 R24: "RES, 750 k, 1%, 0.25 W, 1206"
R26 R38: "RES, 750 k, 1%, 0.1 W, 0603"
R27: "RES, 44.2 k, 1%, 0.1 W, 0603"
R28: "RES, 5.11, 1%, 0.1 W, 0603"
R29: "RES, 1.00 k, 1%, 0.1 W, 0603"
R30: "RES, 47.5, 1%, 0.125 W, 0805"
R31: "RES, 71.5 k, 1%, 0.1 W, 0603"
R32: "RES, 1.50 k, 1%, 0.1 W, 0603"
R34: "RES, 20.5 k, 1%, 0.1 W, 0603"
R35: "RES, 13.7 k, 1%, 0.1 W, 0603"
R37: "RES, 402, 1%, 0.1 W, 0603"
R39: "RES, 0, 5%, 0.1 W, 0603"
RCL1: library part B57236S0100M000, "ICL 4.7 OHM 20% 4.6A 11.51MM"
RV1: "Varistor 275V RMS 10MM Radial, TH"
T1: library part 750314722, "Transformer, 230uH, SMT"
TP1 TP3: "Test Point, Miniature, Red, TH"
TP2 TP4 TP5: "Test Point, Miniature, Black, TH"
U1: "Constant-Voltage, Constant-Current Flyback Controller Using Opto-Coupler Feedback, D0007A"
U2 U4: "Precision VREF Shunt Adjustable"
U3: library part UCC24630DBV, "Sync. Rectifier Controller"
U5: "HIGH SIDE OR-ING FET CONTROLLER"
U6: "Optocoupler, 5 kV, 50-600% CTR, TH-4"
U7: library part TMP300BIDCK, "Low-Power,  Low-Supply  Temperature  Switch"
XF1: "FUSE HOLDER RADIAL 250V 6.3A PCB"
ZZ1: library part AssemblyNoteLabel
ZZ2 ZZ3 ZZ4: library part AssemblyNote

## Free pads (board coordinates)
  oval 20x100 hole 20 slot 100 at 90 deg unplated mask+5: 0(1978,2816.65) 0(1986,2633.65) 0(2384,2817.65) 0(2393,2632.65) 0(3144,2096.65)
  oval 425x20 hole 20 slot 425 at 0 deg unplated mask+5: 0(2181,2776.65) 0(2189,2673.65)
  oval 200x20 hole 20 slot 200 at 0 deg unplated mask+5: 0(3236,2136.65)
  oval 20x200 hole 20 slot 200 at 90 deg unplated mask+5: 0(3458,2112.65)
  oval 300x20 hole 20 slot 300 at 0 deg unplated mask+5: 0(3600,2021.65)
  oval 40x250 hole 40 slot 250 at 90 deg unplated mask+5: 3(2413,271)
  oval 40x120 hole 40 slot 120 at 45 deg unplated rot 135 mask+5: 3(2445,408)
  oval 40x300 hole 40 slot 300 at 90 deg unplated mask+5: 3(2481,574)

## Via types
v1: diameter 24, hole 12, Top Layer to Bottom Layer, tented both sides, 82 vias
v2: diameter 20, hole 10, Top Layer to Bottom Layer, 9 vias

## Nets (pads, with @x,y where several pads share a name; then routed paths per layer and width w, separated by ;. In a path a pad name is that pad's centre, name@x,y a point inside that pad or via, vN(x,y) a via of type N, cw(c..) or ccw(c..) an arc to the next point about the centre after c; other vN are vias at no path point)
AUX1: D1.2 T1.4 | length 166.3
  Bottom Layer w40: T1.4@1405.97,807.39 1456.39,807.39 1490.74,841.74 D1.2@1490.74,909
AUX2: C9.2 T1.5 | length 207.4
  Bottom Layer w40: C9.2@1202,649.57 1397.76,649.57 T1.5@1405.97,657.79
CS: C13.1 Q6.3 R4.1 U1.5 | length 1236.6
  Top Layer w15: v1(228,969) 228,590 314,504 655,504 v1(695,464)
  Bottom Layer w15: v1(228,969) 256.49,997.49 U1.5@367,997.49 C13.1@367,1086.5 ; C13.1@366.5,1087 368,1088.5 R4.1@368,1152.5 ; v1(695,464) 695.48,464.48 Q6.3@727.27,464.48
GND: C1.2 C2.2 C11.2 C13.2 C16.2 C18.2 C20.2 C21.2 C22.2 C34.2 C37.2 HS2.1@1123,516.94 L2.3 Q5.3 R1.1 R2.2 R3.1 R5.2 R10.1 R34.1 T1.6 TP2.1 TP5.1 U1.4 U2.3 U7.1 U7.2 | length 587.5
  Top Layer w30: 228,1093 229,1094 TP5.1@229,1221
  Bottom Layer w15: v1(677.59,913.59) Q5.3@677.59,951.01 ; U2.3@793.7,557.98 v1(793.7,597.3)
  Bottom Layer w20: v1(303.5,1041.5) C13.2@303.5,1087 ; v1(328.49,808.51) U1.4@367,808.51 ; v1(372.73,597.73) R34.1@372.73,642.5 ; v1(437,600) C22.2@437,642.5 ; v1(503,601) R10.1@503,642.5 ; v1(573.8,552.49) R5.2@573.8,595.5 ; v1(585,705) C21.2@585,745.5 ; C16.2@769.5,703 v1(810,703) ; v1(2059.5,67.5) C11.2@2105,67.5
  other v1: 1307,92 1347,92 1327,132 360,160 400,160 380,200 1100,360 100,420 140,420 400,420 440,420 480,420 120,460 96,959 136,979 96,999 136,1019 96,1039 700,1500 740,1500 780,1500
GND-2: C14.1 C26.2 C27.1 C29.2 C30.2 D7.2 HS1.1 L3.3 Q2.3 R8.2 R9.1 R17.2 R19.2 R27.2 R33.2 R36.1 U3.5 U4.3 | length 545
  Bottom Layer w20: v1(2643.47,592.47) R8.2@2643.47,633.5 ; v1(2666,824) 2666.5,824.5 R33.2@2705,824.5 ; C27.1@2708.47,633.5 2709,632.97 v1(2709,593) ; U4.3@2720.27,246.57 v1(2759.43,246.57) ; v1(2793,338) 2793.5,337.5 R27.2@2832.27,337.5 ; C26.2@2848.96,619 v1(2893,619) ; R36.1@2849.96,555 v1(2894,555) ; U3.5@2872.71,716 2945,716 C14.1@2982,753 v1(2982,804.47) ; R17.2@3027.5,880 3027.5,919.5 v1(3028,920) ; D7.2@3084,776.47 v1(3084,817.53)
  other v1: 2779,81 2819,81 2759,121 2799,121 2839,121 2880,1380 2880,1420 2955,1561 2995,1561 3042,1664 3040,1720
GND-3: C17.2 C31.2 C32.2 C33.2 C36.1 D5.2 J2.1 J2.2 L3.1 R11.1 TP4.1 U5.2 U5.3 | length 1768.9
  Top Layer w30: TP4.1@3557,98 3559,100 J2.1@3559,264
  Bottom Layer w10: R11.1@3700,1176.5 3727.27,1149.24 3727.27,1128.7 3727.57,1128.4 3727.57,1078.52 3705.39,1056.35 D5.2@3702.76,1056.35
  Bottom Layer w20: C17.2@3607.25,982.15 C17.2@3607.25,983
  Bottom Layer w30: C36.1@3219.36,2079 3342,1956.36 3342,1500.08 L3.1@3262.96,1421.04 ; J2.2@3559,464 3669,464 3702.76,497.76 D5.2@3702.76,1056.35
  other v1: 3468.85,280 3468.85,340 3468.85,400 3468.85,460 3260,660 3260,700 3260,760 3260,800
GNDE: C5.2 C6.2 C7.2 C8.2 C35.2 C36.2 J1.1 | length 2283
  Top Layer w40: C8.2@1869,2669.29 C7.2@1869,2766.02 ; C6.2@2489,2673.29 C5.2@2489,2779.02
  Bottom Layer w40: C7.2@1869,2766.02 1917.64,2766.02 1958,2725.65 2436.64,2725.65 2703,2459.29 2703,2265.65 2768,2200.65 3052,2200.65 3146,2294.65 J1.1@3563,2294.65
NetBR1_1: BR1.1 L2.1
NetBR1_2: BR1.2 C4.2 C8.1 L1.4
NetBR1_3: BR1.3 RCL1.1
NetBR1_4: BR1.4 L2.4
NetC3_1: C3.1 C5.1 F1.1 L1.2 R22.1 RV1.2 XF1.1
NetC3_2: C3.2 C6.1 J1.2 L1.3 R24.2 RV1.1 | length 118.5
  Bottom Layer w30: C3.2@2924,2428.38 2924,2540.33 R24.2@2928.64,2544.97
NetC4_1: C4.1 C7.1 L1.1 RCL1.2
NetC9_1: C9.1 C10.1 D1.1 D2.2 D3.2 | length 1210
  Top Layer w40: D2.2@1000.89,1301 1247.43,1054.46 C10.1@1247.43,994
  Bottom Layer w40: D2.2@1000.89,1301 935,1366.89 935,1557 1029,1651 D3.2@1136.26,1651 ; C9.1@1202,846.43 1270.69,846.43 D1.1@1333.26,909 ; C10.1@1247.43,994 D1.1@1332.43,909
NetC14_2: C14.2 D7.1 R37.2 U3.6 | length 303.5
  Bottom Layer w20: U3.6@2872.71,678.6 2976.4,678.6 C14.2@2982,673 ; R37.2@2980,594.5 2982,596.5 C14.2@2982,673 ; D7.1@3084,647.53 3083.53,648 3044,648 3019,673 C14.2@2982,673
NetC15_1: C15.1 R15.2 R34.2 U1.3 | length 282
  Bottom Layer w20: R15.2@236.77,706.34 237.77,707.34 C15.1@308.77,707.34 ; 284.5,705.5 R34.2@372.73,705.5 372.73,722.73 417,767 U1.3@417,808.51
NetC15_2: C15.2 R15.1 U6.3 | length 2315.2
  Bottom Layer w20: R15.1@236.77,643.35 236.77,465.23 501,201 U6.3@2192,201
  Bottom Layer w30: R15.1@236.77,643.35 237.77,644.35 C15.2@308.77,644.35
NetC17_1: C17.1 C31.1 C35.1 L3.2 Q3.1 Q3.2 Q3.3 U5.4 | length 937.6
  Top Layer w20: C31.1@3405.43,1174 3479,1174 3504,1149 v1(3504,983)
  Top Layer w30: L3.2@3433.04,1421.04 3489.04,1421.04 3579,1511 3579,1779.36 C35.1@3646,1846.36
  Bottom Layer w20: v1(3504,983) C17.1@3544.26,983 3544.26,1007.7 3528.51,1023.44 U5.4@3528.51,1052.6
NetC19_1: C19.1 Q6.1 R16.1 R25.2 | length 206.5
  Bottom Layer w20: Q6.1@752.86,401.49 773.76,401.49 789.76,385.49 R16.1@819.27,385.49 821.27,383.49 883.27,383.49 886.77,379.98 R25.2@950.42,379.98
NetC22_1: C22.1 R5.1 R10.2 R31.1 U1.2 | length 336.3
  Bottom Layer w20: U1.2@467,808.51 467,760 437,730 C22.1@437,705.5 R10.2@503,705.5 526.8,705.5 R5.1@573.8,658.5 636.29,658.5 R31.1@637.8,656.98
NetC23_1: C23.1 C24.1 R29.1 U4.1 U6.2 | length 508.3
  Bottom Layer w20: U6.2@2492,201 2510.96,219.96 2510.96,408.04 2556.42,453.5 R29.1@2557.27,453.5 2619.34,453.5 C23.1@2621.27,455.42 2621.27,390.5 C24.1@2622.77,389 2622.77,388.15 2682.86,328.06 U4.1@2682.86,317.43
NetC23_2: C23.2 R6.2 | length 70.9
  Bottom Layer w20: C23.2@2684.26,455.42 2752.19,455.42 R6.2@2754.27,457.5
NetC24_2: C24.2 R6.1 R13.1 R14.3 R27.1 U4.2 | length 547.7
  Bottom Layer w20: C24.2@2685.76,389 2748.76,389 R6.1@2754.27,394.5 ; U4.2@2757.67,317.43 2757.67,391.1 R6.1@2754.27,394.5 ; R14.3@3104.06,512 3046.12,454.06 2986.64,454.06 2936.08,403.5 R13.1@2896.27,403.5 2893.27,400.5 R27.1@2832.27,400.5 2826.27,394.5 R6.1@2754.27,394.5
NetC25_1: C25.1 R12.2 R20.2 R32.1 | length 364.3
  Bottom Layer w20: C25.1@2619.34,323 R32.1@2619.34,258 2674.34,203 R20.2@2830.51,203 2830.51,267.27 R12.2@2829.77,268
NetC25_2: C25.2 R29.2 R32.2 U6.1 | length 316.5
  Bottom Layer w20: U6.1@2492,101 2556.35,165.35 R32.2@2556.35,258 C25.2@2556.35,323 2556.35,389.58 R29.2@2557.27,390.5
NetC26_1: C26.1 R36.2 R38.1 U3.1 | length 299.1
  Bottom Layer w20: R36.2@2786.97,555 2786.97,618 C26.1@2785.97,619 2778.22,626.75 U3.1@2778.22,678.6 2808.6,678.6 2817.88,687.88 2817.88,813.63 R38.1@2816,815.5
NetC27_2: C27.2 R8.1 R26.2 U3.2 | length 207.8
  Bottom Layer w20: R26.2@2578.47,696.5 R8.1@2643.47,696.5 C27.2@2708.47,696.5 2727.97,716 U3.2@2778.22,716
NetC28_1: C28.1 R19.1 | length 102.3
  Bottom Layer w20: C28.1@2504,1210 2554,1210 2567,1223 R19.1@2600.91,1223
NetC28_2: C28.2 Q2.2 R38.2 T1.10 | length 106.4
  Bottom Layer w30: R38.2@2816,878.5 2816,975 Q2.2@2823,982
NetC32_1: C32.1 C33.1 D6.1 J2.3 J2.4 Q3.5 Q3.6 Q3.7 Q3.8 Q3.9 R7.1 TP3.1 U5.6 | length 1400.2
  Top Layer w15: J2.4@3559,864 3675,864 3725.5,914.5 3725.5,1367.71 D6.1@3677,1416.21
  Top Layer w20: 3509,873 3509,922 3545,958 3545,1136 v1(3637,1228) ; D6.1@3677,1416.21 3677,1527 TP3.1@3679,1529
  Bottom Layer w20: U5.6@3528.51,1127.4 3528.51,1156.01 R7.1@3560.5,1188 3560.5,1188.85 3596.36,1224.7 3637,1224.7 v1(3637,1228)
  other v2: 3292.87,937.03 3354.69,937.03 3410,937.03 3292.87,988 3354.69,988 3410,988 3292.87,1036.62 3354.69,1036.62 3410,1036.62
NetD4_1: D4.1 R30.2 | length 152.8
  Bottom Layer w20: D4.1@2161.4,412.76 2223.76,412.76 2246,435 R30.2@2246,494
NetD5_1: D5.1 R7.2 U5.1 | length 152.1
  Bottom Layer w20: R7.2@3623.5,1188 3623,1187.5 U5.1@3623,1127.4 3652.6,1127.4 3680.35,1099.65 D5.1@3702.76,1099.65
NetD6_2: D6.2 R11.2 | length 87.8
  Bottom Layer w20: D6.2@3677,1317.79 3677,1262.5 R11.2@3700,1239.5
NetF1_2: F1.2 J1.3 XF1.2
